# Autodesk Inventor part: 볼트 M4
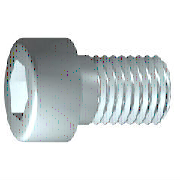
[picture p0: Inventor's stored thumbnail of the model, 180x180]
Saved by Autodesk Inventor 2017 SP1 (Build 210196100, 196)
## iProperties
IsCustomPart: 0
Created: 2018-09
Part Number: 볼트 M4
Material: 스테인리스강
Description: 6각머리 태핑 나사
Document SubType Name: Modeling
Standard: KS B 1003
Standards Organization: KS
Language: ko-KR
Size Designation: M 4 x 10
Categories: <MemberInstance><Categories><Category DisplayName="조임쇠" InternalName="e4da775c-781d-43d5-af7c-5136215cf5a6" Mnemonic="FSTN"><Category DisplayName="볼트" InternalN
Density: 8.08 g/cm^3
Mass: 2.09412 g
Surface Area: 3.0572 cm^2
Volume: 0.259174 cm^3
Appearance: 반광택
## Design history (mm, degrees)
sketch "스케치1"
  geometry: L1 (-1, 0)-(10, 0); L2 (10, 0)-(10, 2); L3 (10, 2)-(1.75, 2); L4 (1.75, 2)-(1.32, 2); L5 (1.32, 2)-(0, 2); L6 (0, 2)-(0, 3.5); L7 (0, 3.5)-(-4, 3.5); L8 (-4, 3.5)-(-4, 1.732); L9 (-4, 1.732)-(-2, 1.732); L10 (-2, 1.732)-(-1, 0); L11 (-6.8, 0)-(12.8, 0) reference; L12 (0, -0.7)-(0, 4.2) reference; L13 (1.75, 2)-(0, 2)
  constraints: 22 end point, 6 parallel, 2 collinear, 2 perpendicular, 1 horizontal, 1 point on line
  dimensions: "d1" = 8.25 distance from line of L3.end L2 (= GEL); "d2" = 0.42952 distance of L4.end L3.end (computed from GAL); "d3" = 4 distance between parallel lines of L8 L6 (= KOH); "d4" = 2 distance of L8.end L9.end (= INTI); "d5" = 60 deg angle of L10 L1; "d6" = 4 diameter of L3 L1 (= GD); "d7" = 4 diameter of L5 L1 (= BDM); "d8" = 3.4641 diameter of L9 L1 (= 1.1547 x SW); "d9" = 7 diameter of L7 L1 (= KOD); "d26" = 10 distance between parallel lines of L12 L2 (= NLG)
revolve "본체" sketch "스케치1" stored, may be unused: angle "d10" = 90 deg
sketch "스케치2"
  geometry: L1 (0, -4.9)-(0, 4.9) reference; L2 (-4.9, 0)-(4.9, 0) reference; L3 (1.732, 0)-(0.866, -1.5); L4 (0.866, -1.5)-(-0.866, -1.5); L5 (-0.866, -1.5)-(-1.732, 0); L6 (-1.732, 0)-(-0.866, 1.5); L7 (-0.866, 1.5)-(0.866, 1.5); L8 (0.866, 1.5)-(1.732, 0); 2 further points
  constraints: 12 end point, 1 coincident, 1 horizontal alignment, 1 point on line, 12 other
extrude "슬롯" join sketch "스케치2" stored distance "d11" = 10; taper "d12" = 0 deg
workplane "Work Plane1"
fillet "Fillet2" dims "d30" = 0.1 (= R)
body "Solid1"
fillet "모깎기1" dims "d17" = 0.4 (= RR)
feature "스레드" dims "d13" = 8.25 (= GEL), "d14" = 0
chamfer "모따기1" distance "d15" = 0.42941 (= -0.5 x SPD + 0.5 x GD); stored, may be unused: second distance "d16" = 0.42941 (= GUL), angle "d27" = 45 deg
other parameters: "GD" = 4 (= NND) [user parameter; used in 2 equation terms], "NLG" = 10 [user parameter; used in 1 equation term], "GEL" = 8.25 [user parameter; used in 2 equation terms], "KOD" = 7 [user parameter; used in 1 equation term], "KOH" = 4 [user parameter; used in 1 equation term], "INTI" = 2 [user parameter; used in 1 equation term], "GAL" = 0.42941 (= 0.61345 x PTC) [user parameter; used in 1 equation term], "GUL" = 0.42941 (= 0.61345 x PTC) [user parameter; used in 1 equation term], "BDM" = 4 (= NND) [user parameter; used in 1 equation term], "SW" = 3 [user parameter; used in 2 equation terms], "RR" = 0.4 [user parameter; used in 1 equation term], "SPD" = 3.14117 (= NND - 1.2269 x PTC) [user parameter; used in 1 equation term], "d19" = 0, "d28" = 0, "d29" = 0, "R" = 0.1 [user parameter; used in 1 equation term], "PHH" = 0.2 [user parameter], "GD1" = 3.14117 (= THREADDIA - 1.2269 x PTC) [user parameter], "THREADDIA" = 4 [user parameter; used in 1 equation term], "FAWI" = 45 deg [user parameter], "TPU" = 14.28571 (computed from PTC) [user parameter], "PTC" = 0.7 [user parameter; used in 5 equation terms], "NND" = 4 [user parameter; used in 3 equation terms], "TOA" = 30 deg [user parameter], "E0" = 3.465 (= 1.155 x SW) [user parameter]
